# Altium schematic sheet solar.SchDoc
size A4
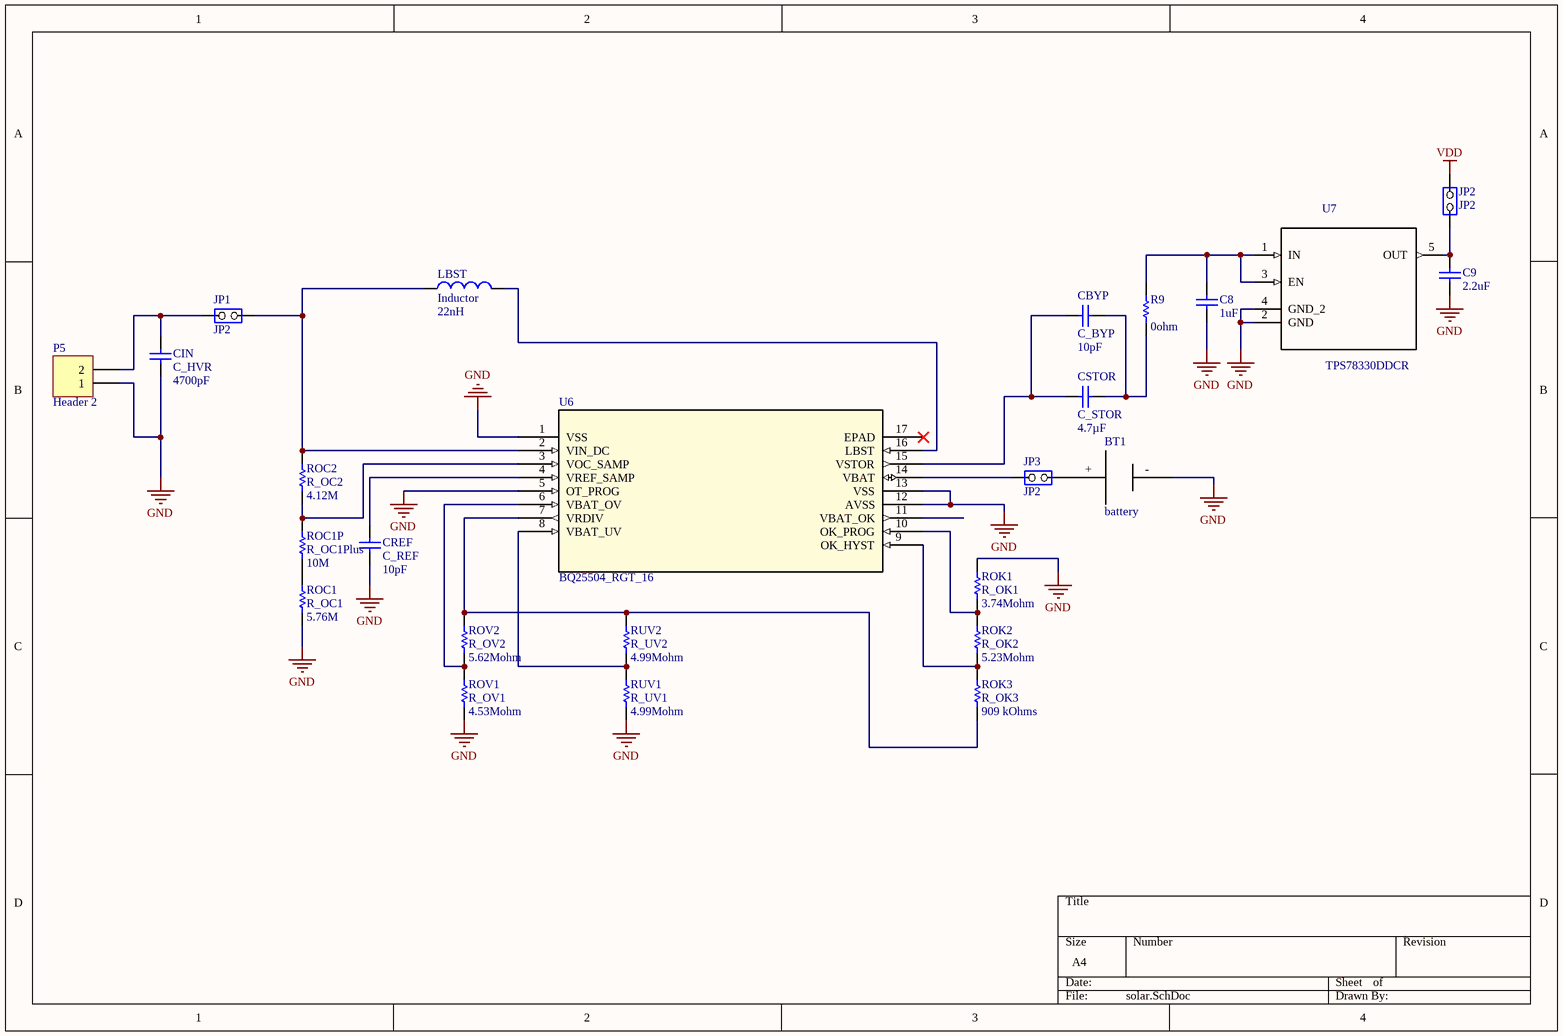
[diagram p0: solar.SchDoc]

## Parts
BT1  battery  [BATTERY]
C8  1uF  [0603C]
C9  2.2uF  [0603C]
CBYP  C_BYP  value 10pF  [0603C]
CIN  C_HVR  value 4700pF  [0603C]
CREF  C_REF  value 10pF  [0603C]
CSTOR  C_STOR  value 4.7µF  [0603C]
JP1  JP2  [SIP2/2.54]
JP2  JP2  [SIP2/2.54]
JP3  JP2  [SIP2/2.54]
LBST  Inductor  value 22nH  [INDC1608L]
P5  Header 2  [HDR1X2]
R9  value 0ohm  [0603R]
ROC1  R_OC1  value 5.76M  [0603R]
ROC1P  R_OC1Plus  value 10M  [0603R]
ROC2  R_OC2  value 4.12M  [0603R]
ROK1  R_OK1  value 3.74Mohm  [0603R]
ROK2  R_OK2  value 5.23Mohm  [0603R]
ROK3  R_OK3  value 909 kOhms  [0603R]
ROV1  R_OV1  value 4.53Mohm  [0603R]
ROV2  R_OV2  value 5.62Mohm  [0603R]
RUV1  R_UV1  value 4.99Mohm  [0603R]
RUV2  R_UV2  value 4.99Mohm  [0603R]
U6  BQ25504_RGT_16  [RGT16_1P7X1P7]
U7  TPS78330DDCR  [SOT95P280X110-5N]

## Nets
GND: BT1.- C8.1 C9.1 CIN.1 CREF.1 P5.1 ROC1.1 ROK1.2 ROV1.1 RUV1.1 U6.1(VSS) U6.5(OT_PROG) U6.12(AVSS) U6.13(VSS) U7.2(GND) U7.4(GND_2)
VDD: JP2.2(NO)
NetBT1_+: BT1.+ JP3.2(NO)
NetC8_2: C8.2 R9.2 U7.1(IN) U7.3(EN)
NetC9_2: C9.2 JP2.1(COMMON) U7.5(OUT)
NetCBYP_1: CBYP.1 CSTOR.1 U6.15(VSTOR)
NetCBYP_2: CBYP.2 CSTOR.2 R9.1
NetCIN_2: CIN.2 JP1.1(COMMON) P5.2
NetCREF_2: CREF.2 U6.4(VREF_SAMP)
NetJP1_2: JP1.2(NO) LBST.1 ROC2.2 U6.2(VIN_DC)
NetJP3_1: JP3.1(COMMON) U6.14(VBAT)
NetLBST_2: LBST.2 U6.16(LBST)
NetROC1_2: ROC1.2 ROC1P.1
NetROC1P_2: ROC1P.2 ROC2.1 U6.3(VOC_SAMP)
NetROK1_1: ROK1.1 ROK2.2 U6.10(OK_PROG)
NetROK2_1: ROK2.1 ROK3.2 U6.9(OK_HYST)
NetROK3_1: ROK3.1 ROV2.2 RUV2.2 U6.7(VRDIV)
NetROV1_2: ROV1.2 ROV2.1 U6.6(VBAT_OV)
NetRUV1_2: RUV1.2 RUV2.1 U6.8(VBAT_UV)

Not connected (* = marked no-connect by the designer): U6 11(VBAT_OK) 17(EPAD)*

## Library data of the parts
BT1 = battery: Manufacturer: Harwin Inc.; ProductNumber: M20-9990246; Vendor name: Digikey; Vendor PN: 952-2262-ND
C8 = Cap: Capacitor; Manufacturer: AVX Corporation; Value: 1000pF; ProductNumber: 06035C102KAT2A; Vendor name: Digikey; Vendor PN: 478-1215-1-ND
C9 = Cap: Capacitor; Manufacturer: Murata Electronics North America; Value: 2.2µF; ProductNumber: GRM188R61C225KE15D; Vendor name: Digikey; Vendor PN: 490-3296-1-ND
CBYP CREF = Cap: Capacitor; Manufacturer: Murata Electronics North America; ProductNumber: GRM1885C1H100JA01D; Vendor name: Digikey; Vendor PN: 490-1403-1-ND
CIN = Cap: Capacitor; Manufacturer: TDK; ProductNumber: C1608NP01H472J080AA; Vendor name: Digikey; Vendor PN: 445-14083-1-ND
CSTOR = Cap: Capacitor; Manufacturer: Taiyo Yuden; ProductNumber: JMK107BJ475KA-T; Vendor name: Digikey; Vendor PN: 587-1785-1-ND
JP1-JP3 = JP2: Manufacturer: Harwin Inc.; ProductNumber: M20-9990246; Vendor name: Digikey; Vendor PN: 952-2262-ND
LBST = Inductor: Manufacturer: Johanson Technology; Code_IEC: 1005; ProductNumber: L-14C22NJV4T; Vendor name: Digikey; Vendor PN: 712-1438-1-ND
P5 = Header 2: Header, 2-Pin; Manufacturer: Harwin Inc.; ProductNumber: M20-9990246; Vendor name: Digikey; Vendor PN: 952-2262-ND
R9 = Res1: Resistor; Manufacturer: Yageo; ProductNumber: RC0603JR-070RL; Vendor name: Digikey; Vendor PN: 311-0.0GRCT-ND
ROC1 = Res1: Resistor; Manufacturer: Vishay Dale; ProductNumber: CRCW06035M76FKEA; Vendor name: Digikey; Vendor PN: 541-5.76MHCT-ND
ROC1P = Res1: Resistor; Manufacturer: Yageo; ProductNumber: RC0603JR-0710ML; Vendor name: Digikey; Vendor PN: 311-10MGRCT-ND
ROC2 = Res1: Resistor; Manufacturer: Vishay Dale; ProductNumber: CRCW06034M12FKEA; Vendor name: Digikey; Vendor PN: 541-4.12MHCT-ND
ROK1 = Res1: Resistor; Manufacturer: Stackpole Electronics Inc.; ProductNumber: RMCF0603FT3M74; Vendor name: Digikey; Vendor PN: RMCF0603FT3M74CT-ND
ROK2 = Res1: Resistor; Manufacturer: Vishay Dale; ProductNumber: CRCW06035M23FKEA; Vendor name: Digikey; Vendor PN: 541-5.23MHCT-ND
ROK3 = Res1: Resistor; Manufacturer: Yageo; ProductNumber: RC0603FR-07909KL; Vendor name: Digikey; Vendor PN: 311-909KHRCT-ND
ROV1 = Res1: Resistor; Manufacturer: Stackpole Electronics Inc.; ProductNumber: RMCF0603FT4M53; Vendor name: Digikey; Vendor PN: RMCF0603FT4M53CT-ND
ROV2 = Res1: Resistor; Manufacturer: Stackpole Electronics Inc.; ProductNumber: RMCF0603FT5M62; Vendor name: Digikey; Vendor PN: RMCF0603FT5M62CT-ND
RUV1 RUV2 = Res1: Resistor; Manufacturer: Vishay Dale; ProductNumber: CRCW06034M99FKEA; Vendor name: Digikey; Vendor PN: 541-4.99MHCT-ND
U6 = BQ25504_RGT_16: Imported; Manufacturer: Texas Instruments; INDUSTRY_STD_PKG_TYPE: QFN; FAMILY_NAME: BATTERY CHARGE MANAGEMENT; PIN_COUNT: 16; PACKAGE_DESIGNATOR: RGT; ProductNumber: BQ25504RGTT; Vendor name: Digikey; Vendor PN: 296-29741-1-ND
U7 = TPS78330DDCR: IC REG LINEAR 3V 150MA SOT23-5; MF: Texas Instruments; Vendor name: Digikey; Vendor PN: 296-25880-1-ND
